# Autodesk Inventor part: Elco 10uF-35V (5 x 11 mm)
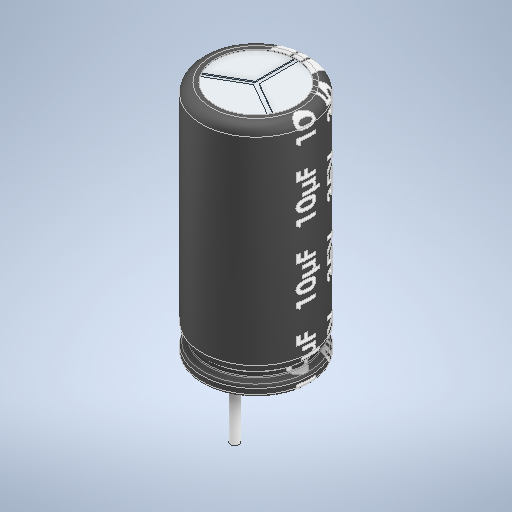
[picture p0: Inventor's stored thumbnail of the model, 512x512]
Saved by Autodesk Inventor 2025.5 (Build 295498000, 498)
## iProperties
Created: 2024-02
Part Number: Elco 10uF-35V (5 x 11 mm)
Material: Genérico
Description: STEP AP214
Document SubType Name: Modeling
Designer: Luis M
Density: 1 g/cm^3
Appearance: Valor por defecto
Preprocessor: SwSTEP 2.0
Title: Elco 10uF-35V (5 x 11 mm).STEP
Author: M.B.I.
Revision Number: ANY
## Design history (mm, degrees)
fillet "Cut-Extrude1"
fillet "Fillet2"
fillet "Boss-Extrude2[2]"
fillet "Cut-Extrude3"
fillet "Split Line2"
sketch "Boceto1"
  geometry: C1 r 5.208 at (0.214, -0.354); 1 further point
  constraints: 1 centre point
extrude "Extrusión1" cut sketch "Boceto1" distance "d0" = 17; taper "d1" = 0 deg
sketch "Boceto2"
  geometry: C1 r 1.107 at (-0.657, 0.245); 1 further point
  constraints: 1 centre point
extrude "Extrusión2" cut sketch "Boceto2" distance "d2" = 13.5; taper "d3" = 0 deg
node "Sólido1"
node "Sólido2"
node "Sólido3"
node "Sólido4"
node "Sólido5"
